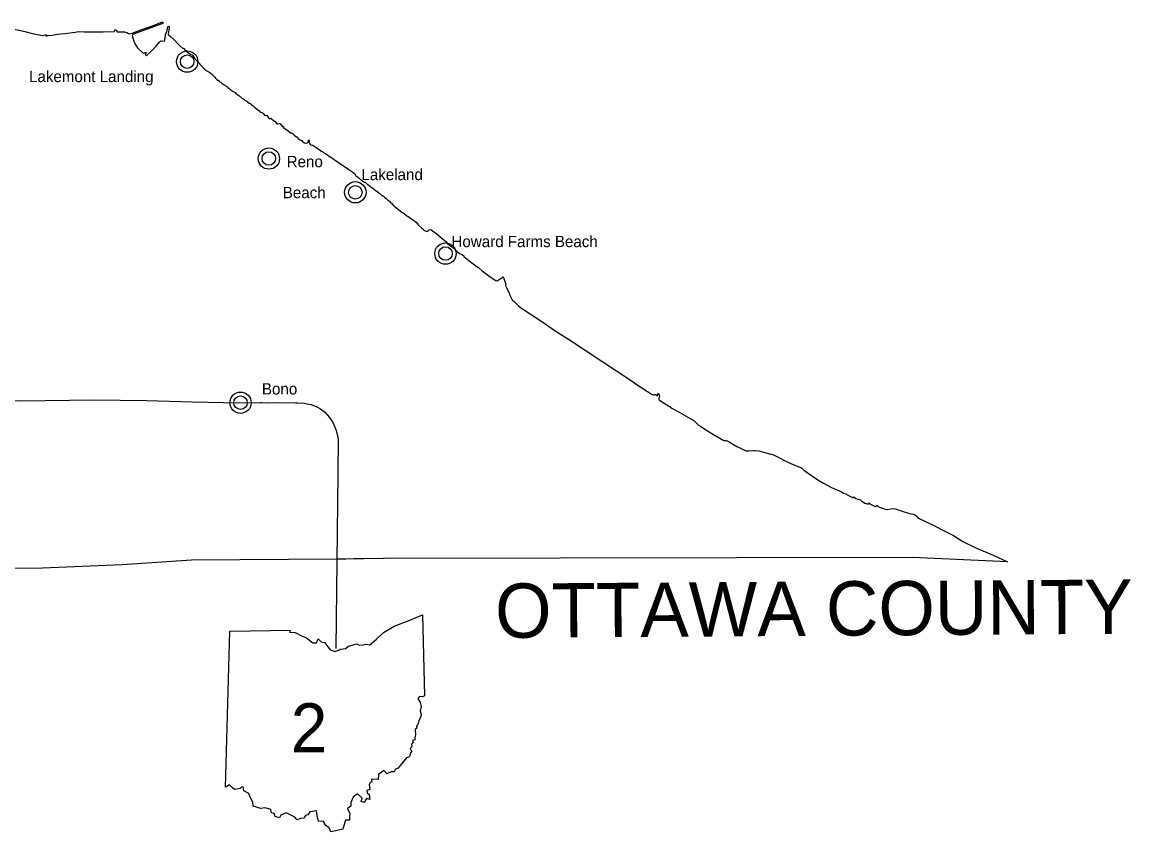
# Model space of a CAD drawing. Extents: x 0 to 750, y 0 to 507.
# Drawn here: x 515.6 to 617.7, y 213.2 to 287.8 of the extents above; entities that cross this region are included whole.
import ezdxf

# ---------------------------------------------------------------- set-up
doc = ezdxf.new("R2010")
doc.units = 0
for name, color, linetype in [('DV_X_Corp_Line', 7, 'Continuous'), ('GM_X_Adjacent_County_Text', 7, 'Continuous'), ('GM_X_County', 7, 'Continuous'), ('GM_X_Interstate_Route', 7, 'Continuous'), ('GM_X_State_Route', 7, 'Continuous')]:
    doc.layers.add(name, color=color, linetype=linetype)

msp = doc.modelspace()

# ---------------------------------------------------------------- linework, layer by layer
at = {"layer": 'DV_X_Corp_Line'}
for centre, radius in [((530.83, 284.15), 0.982), ((530.83, 284.15), 0.623), ((538.35, 275.22), 0.982), ((538.35, 275.22), 0.623), ((546.31, 272.11), 0.982), ((546.31, 272.11), 0.623), ((554.61, 266.47), 0.982), ((554.61, 266.47), 0.623), ((535.74, 252.73), 0.982), ((535.74, 252.73), 0.623)]:
    msp.add_circle(centre, radius, dxfattribs=at)
at = {"layer": 'GM_X_County'}
msp.add_lwpolyline([(514.76, 287.16), (515.77, 286.94), (516.58, 286.73), (517.19, 286.6), (517.49, 286.56), (517.6, 286.58), (517.77, 286.6), (517.83, 286.6), (517.9, 286.59), (517.91, 286.57), (517.83, 286.52), (517.86, 286.52), (517.94, 286.52), (518.03, 286.55), (518.39, 286.58), (518.9, 286.66), (519.19, 286.7), (519.58, 286.73), (520.53, 286.87), (520.87, 286.91), (521.38, 286.9), (521.62, 286.9), (522.02, 286.89), (522.31, 286.89), (522.6, 286.9), (523.1, 286.88), (524.1, 286.91), (524.13, 286.91), (524.16, 287.04), (524.18, 287.07), (524.24, 287.08), (524.3, 287.05), (524.34, 287), (524.35, 286.93), (524.38, 286.9), (524.92, 286.89), (525.07, 286.89), (525.28, 286.83), (525.42, 286.74), (525.49, 286.71), (525.78, 286.76), (526.57, 287.06), (527.21, 287.3), (527.8, 287.49), (528.5, 287.78), (528.55, 287.78), (528.6, 287.75), (528.62, 287.72), (528.6, 287.67), (525.81, 286.64), (525.79, 286.61), (525.77, 286.55), (525.82, 286.33), (525.91, 286.04), (526.06, 285.69), (526.27, 285.42), (526.75, 284.95), (526.83, 284.92), (526.91, 284.95), (526.98, 285), (527.03, 285.01), (527.05, 284.97), (526.98, 284.9), (526.97, 284.79), (527.07, 284.69), (527.15, 284.75), (527.19, 284.8), (527.46, 285.04), (527.98, 285.58), (528.1, 285.71), (528.27, 285.93), (528.36, 286.02), (528.44, 286.07), (528.74, 286.04), (528.86, 286.73), (528.92, 286.83), (528.96, 286.89), (529.01, 287.19), (529.04, 287.37), (529.07, 287.39), (529.13, 287.41), (529.17, 287.38), (529.18, 287.29), (529.14, 287.06), (529.09, 286.64), (529.12, 286.61), (529.26, 286.5), (529.53, 286.24), (530.1, 285.67), (530.41, 285.4), (530.45, 285.39), (530.52, 285.37), (530.54, 285.32), (530.6, 285.24), (530.7, 285.16), (530.76, 285.08), (530.8, 285.05), (530.88, 284.99), (530.96, 284.97), (531.17, 284.81), (531.3, 284.77), (531.33, 284.74), (531.38, 284.65), (531.5, 284.47), (531.6, 284.38), (531.6, 284.34), (531.7, 284.24), (531.91, 284.02), (531.95, 284), (531.95, 283.95), (532.09, 283.81), (532.37, 283.51), (532.45, 283.48), (532.44, 283.45), (532.5, 283.39), (532.91, 283.13), (533.03, 283.05), (533.17, 282.94), (533.24, 282.86), (533.31, 282.75), (533.38, 282.73), (533.37, 282.71), (533.45, 282.62), (533.56, 282.51), (533.65, 282.45), (533.72, 282.44), (533.72, 282.4), (533.79, 282.31), (533.92, 282.24), (534.03, 282.16), (534.17, 282.05), (534.27, 282), (534.32, 281.96), (534.44, 281.88), (534.5, 281.83), (534.56, 281.76), (534.64, 281.71), (534.71, 281.69), (534.72, 281.65), (534.83, 281.55), (534.9, 281.53), (534.92, 281.49), (535, 281.43), (535.14, 281.35), (535.25, 281.29), (535.31, 281.22), (535.54, 281.06), (535.85, 280.79), (535.98, 280.71), (536.03, 280.71), (536.17, 280.58), (536.25, 280.55), (536.29, 280.55), (536.41, 280.41), (536.55, 280.33), (536.6, 280.31), (536.71, 280.2), (536.89, 280.09), (537.02, 279.95), (537.42, 279.65), (537.56, 279.5), (537.73, 279.45), (537.82, 279.37), (537.96, 279.23), (538.06, 279.17), (538.1, 279.2), (538.15, 279.19), (538.33, 278.98), (538.48, 278.89), (538.52, 278.93), (538.6, 278.88), (538.74, 278.75), (538.86, 278.65), (538.89, 278.67), (538.94, 278.62), (539.04, 278.49), (539.13, 278.43), (539.19, 278.43), (539.29, 278.45), (539.36, 278.44), (539.57, 278.21), (539.63, 278.17), (539.69, 278.17), (539.7, 278.15), (539.68, 278.12), (539.84, 277.97), (540.09, 277.81), (540.34, 277.6), (540.4, 277.59), (540.43, 277.59), (540.51, 277.52), (540.58, 277.49), (540.63, 277.49), (540.69, 277.38), (540.89, 277.23), (540.96, 277.18), (541.05, 277.08), (541.31, 276.89), (541.38, 276.87), (541.46, 276.8), (541.64, 276.68), (541.8, 276.65), (541.92, 276.66), (541.97, 276.74), (542.01, 276.92), (542.07, 276.9), (542.06, 276.69), (542.13, 276.57), (542.19, 276.49), (542.36, 276.44), (542.43, 276.42), (542.68, 276.27), (543.19, 275.91), (543.42, 275.77), (543.87, 275.47), (544.86, 274.78), (545.72, 274.2), (546.08, 273.96), (546.27, 273.81), (546.31, 273.75), (546.37, 273.62), (546.4, 273.61), (546.5, 273.55), (546.55, 273.51), (546.62, 273.44), (546.75, 273.32), (546.8, 273.3), (546.98, 273.16), (547.09, 273.07), (547.13, 273.05), (547.18, 273.06), (547.25, 273), (547.41, 272.86), (547.47, 272.82), (547.59, 272.75), (547.73, 272.61), (547.83, 272.55), (547.88, 272.52), (548.1, 272.33), (548.21, 272.28), (548.33, 272.18), (548.43, 272.09), (548.51, 272.04), (548.56, 272), (548.73, 271.84), (548.8, 271.8), (548.86, 271.79), (548.96, 271.7), (549.03, 271.63), (549.14, 271.54), (549.22, 271.49), (549.27, 271.43), (549.4, 271.34), (549.47, 271.32), (549.46, 271.28), (549.52, 271.2), (549.67, 271.08), (549.8, 270.92), (550.24, 270.56), (550.49, 270.34), (550.64, 270.25), (550.76, 270.19), (550.85, 270.12), (551.06, 269.94), (551.14, 269.91), (551.28, 269.83), (551.78, 269.45), (551.96, 269.29), (552.1, 269.12), (552.43, 268.82), (552.75, 268.57), (552.92, 268.51), (552.99, 268.52), (553.04, 268.59), (553.1, 268.65), (553.19, 268.68), (553.28, 268.66), (553.73, 268.35), (554.63, 267.58), (554.79, 267.4), (555.17, 267.1), (555.26, 267.05), (555.33, 266.96), (555.38, 266.94), (555.64, 266.69), (555.91, 266.48), (556.04, 266.4), (556.15, 266.37), (556.29, 266.25), (556.31, 266.2), (556.62, 265.96), (556.76, 265.83), (557.29, 265.43), (557.56, 265.23), (557.61, 265.22), (557.71, 265.12), (558, 264.89), (558.72, 264.34), (559.23, 264), (559.36, 263.97), (559.46, 264.03), (559.82, 264.28), (559.89, 264.33), (559.93, 264.32), (559.96, 264.25), (560.07, 263.91), (560.17, 263.68), (560.15, 263.64), (560.13, 263.59), (560.12, 263.54), (560.25, 263.28), (560.46, 262.82), (560.53, 262.63), (560.61, 262.44), (560.76, 262.22), (560.95, 262.01), (561.33, 261.67), (561.62, 261.43), (563.29, 260.33), (563.8, 260), (564.81, 259.3), (565.93, 258.6), (568.99, 256.56), (571.7, 254.77), (572.25, 254.39), (573.65, 253.48), (573.76, 253.45), (573.84, 253.46), (573.92, 253.51), (574.06, 253.41), (574.1, 253.41), (574.15, 253.41), (574.13, 253.48), (574.12, 253.52), (574.16, 253.56), (574.2, 253.57), (574.29, 253.46), (574.31, 253.29), (574.28, 253.21), (574.25, 253.11), (574.25, 253.04), (574.41, 252.91), (575.22, 252.39), (575.29, 252.38), (575.33, 252.32), (575.45, 252.22), (576.12, 251.85), (576.78, 251.48), (576.99, 251.38), (577.48, 251.09), (577.7, 250.87), (577.86, 250.71), (578.08, 250.56), (578.49, 250.3), (579.28, 249.82), (580.22, 249.26), (580.33, 249.26), (580.48, 249.24), (580.71, 249.13), (581.42, 248.71), (581.84, 248.52), (582.13, 248.36), (582.25, 248.31), (582.54, 248.31), (582.98, 248.34), (583.13, 248.34), (583.44, 248.29), (584.22, 248.1), (584.57, 247.99), (584.73, 247.97), (585.04, 247.82), (585.31, 247.69), (585.94, 247.36), (586.69, 247), (587.37, 246.74), (587.61, 246.52), (588.31, 246.02), (588.49, 245.9), (588.89, 245.62), (589.41, 245.31), (590.14, 244.93), (590.79, 244.64), (590.82, 244.66), (590.99, 244.56), (591.13, 244.48), (591.26, 244.41), (591.38, 244.36), (591.49, 244.34), (591.48, 244.31), (591.7, 244.2), (591.94, 244.06), (592.15, 243.98), (592.21, 244.08), (592.39, 243.92), (592.8, 243.78), (592.9, 243.71), (593.22, 243.49), (593.54, 243.4), (593.58, 243.5), (593.72, 243.4), (593.92, 243.31), (594.09, 243.21), (594.24, 243.19), (594.29, 243.24), (594.32, 243.28), (594.36, 243.3), (594.37, 243.25), (594.42, 243.17), (594.57, 243.1), (594.92, 242.99), (595.1, 242.92), (595.3, 242.89), (595.58, 242.95), (595.82, 242.98), (596, 242.95), (596.73, 242.7), (597.33, 242.53), (597.7, 242.48), (597.79, 242.45), (597.88, 242.38), (598, 242.24), (598.09, 242.14), (598.27, 242.05), (598.68, 241.86), (599.68, 241.35), (600.47, 240.97), (601.39, 240.49), (602.23, 239.96), (603.48, 239.35), (605.04, 238.69), (606.34, 238.09), (597.6, 238.48), (548.96, 238.38), (548.84, 238.38), (547.11, 238.35), (546.2, 238.35), (545.43, 238.34), (544.61, 238.32), (531.24, 238.24), (524.85, 237.8), (517.5, 237.5), (504.51, 237.37)], dxfattribs=at)
at = {"layer": 'GM_X_Interstate_Route'}
msp.add_line((534.37, 217.32), (534.77, 231.68), dxfattribs=at)
msp.add_line((534.37, 217.32), (534.77, 231.68), dxfattribs=at)
for points in [[(534.77, 231.68), (540.34, 231.78), (540.26, 231.6), (540.78, 231.57), (541.34, 231.26), (541.81, 231.07), (542.39, 230.61), (542.74, 230.61), (542.88, 230.99), (543.15, 230.7), (543.46, 230.65), (544, 229.96), (544.45, 229.81), (544.99, 230.05), (545.39, 230.09), (545.69, 230.32), (546.45, 230.52), (546.66, 230.4), (547.07, 230.42), (547.27, 230.51), (547.63, 230.43), (548.25, 230.95), (548.89, 231.57), (549.87, 232.15), (551.34, 232.7), (552.5, 233.19), (552.67, 225.74)], [(534.77, 231.68), (540.34, 231.78), (540.26, 231.6), (540.78, 231.57), (541.34, 231.26), (541.81, 231.07), (542.39, 230.61), (542.74, 230.61), (542.88, 230.99), (543.15, 230.7), (543.46, 230.65), (544, 229.96), (544.45, 229.81), (544.99, 230.05), (545.39, 230.09), (545.69, 230.32), (546.45, 230.52), (546.66, 230.4), (547.07, 230.42), (547.27, 230.51), (547.63, 230.43), (548.25, 230.95), (548.89, 231.57), (549.87, 232.15), (551.34, 232.7), (552.5, 233.19), (552.67, 225.74)], [(552.67, 225.74), (552.5, 225.64), (552.23, 225.68), (552.05, 225.48), (552.28, 225.13), (552.38, 224.76), (552.29, 224.35), (552.38, 224.02), (552.32, 223.74), (552.15, 223.46), (552.09, 223.19), (551.95, 222.91), (551.96, 222.75), (551.82, 222.63), (551.85, 222.16), (551.78, 221.91), (551.8, 221.68), (551.58, 221.62), (551.63, 221.44), (551.49, 221.3), (551.52, 221.05), (551.36, 220.9), (551.52, 220.58), (551.39, 220.49), (551.29, 220.11), (551.01, 220.03), (550.44, 219.33), (550.24, 219.07), (550.02, 219), (549.89, 218.73), (549.62, 218.73), (549.2, 218.55), (548.93, 218.87), (548.45, 218.48), (548.4, 218.03), (547.8, 218.05), (547.82, 217.82), (547.69, 217.75), (547.57, 217.53), (547.64, 217.12), (547.36, 217.02), (547.39, 216.79), (547.57, 216.64), (547.65, 216.2), (547.35, 216.29), (547.11, 215.91), (546.86, 216), (546.94, 216.32), (546.51, 216.7), (546.11, 216.4), (545.9, 215.9), (545.9, 215.57), (545.6, 215.37), (545.79, 214.91), (545.76, 214.58), (545.76, 214.28), (545.39, 214.29), (545.16, 213.47)], [(552.67, 225.74), (552.5, 225.64), (552.23, 225.68), (552.05, 225.48), (552.28, 225.13), (552.38, 224.76), (552.29, 224.35), (552.38, 224.02), (552.32, 223.74), (552.15, 223.46), (552.09, 223.19), (551.95, 222.91), (551.96, 222.75), (551.82, 222.63), (551.85, 222.16), (551.78, 221.91), (551.8, 221.68), (551.58, 221.62), (551.63, 221.44), (551.49, 221.3), (551.52, 221.05), (551.36, 220.9), (551.52, 220.58), (551.39, 220.49), (551.29, 220.11), (551.01, 220.03), (550.44, 219.33), (550.24, 219.07), (550.02, 219), (549.89, 218.73), (549.62, 218.73), (549.2, 218.55), (548.93, 218.87), (548.45, 218.48), (548.4, 218.03), (547.8, 218.05), (547.82, 217.82), (547.69, 217.75), (547.57, 217.53), (547.64, 217.12), (547.36, 217.02), (547.39, 216.79), (547.57, 216.64), (547.65, 216.2), (547.35, 216.29), (547.11, 215.91), (546.86, 216), (546.94, 216.32), (546.51, 216.7), (546.11, 216.4), (545.9, 215.9), (545.9, 215.57), (545.6, 215.37), (545.79, 214.91), (545.76, 214.58), (545.76, 214.28), (545.39, 214.29), (545.16, 213.47)], [(545.16, 213.47), (544.51, 213.31), (544.06, 213.21), (543.9, 213.59), (543.58, 213.79), (543.37, 214.16), (542.91, 214.21), (542.8, 214.73), (542.74, 215.15), (542.11, 215.05), (541.94, 214.79), (541.71, 214.72), (541.58, 214.46), (541.27, 214.44), (540.95, 214.32), (540.73, 214.57), (540.19, 214.83), (539.95, 214.96), (539.44, 214.76), (539.34, 214.51), (538.93, 214.62), (538.84, 214.89), (538.59, 214.97), (538.54, 215.26), (538.02, 215.41), (537.62, 215.35), (536.92, 215.58), (536.87, 215.96), (536.63, 216.41), (536.51, 216.73), (536.06, 216.98), (535.97, 217.35), (535.83, 217.34), (535.7, 217.19), (535.21, 217.12), (535.01, 217.27), (534.73, 217.54), (534.37, 217.32)], [(545.16, 213.47), (544.51, 213.31), (544.06, 213.21), (543.9, 213.59), (543.58, 213.79), (543.37, 214.16), (542.91, 214.21), (542.8, 214.73), (542.74, 215.15), (542.11, 215.05), (541.94, 214.79), (541.71, 214.72), (541.58, 214.46), (541.27, 214.44), (540.95, 214.32), (540.73, 214.57), (540.19, 214.83), (539.95, 214.96), (539.44, 214.76), (539.34, 214.51), (538.93, 214.62), (538.84, 214.89), (538.59, 214.97), (538.54, 215.26), (538.02, 215.41), (537.62, 215.35), (536.92, 215.58), (536.87, 215.96), (536.63, 216.41), (536.51, 216.73), (536.06, 216.98), (535.97, 217.35), (535.83, 217.34), (535.7, 217.19), (535.21, 217.12), (535.01, 217.27), (534.73, 217.54), (534.37, 217.32)]]:
    msp.add_lwpolyline(points, dxfattribs=at)
at = {"layer": 'GM_X_State_Route'}
for points in [[(495.54, 252.94), (508.9, 252.95), (515.51, 252.91), (522.24, 252.99)], [(522.24, 252.99), (527.09, 252.93), (531.28, 252.8), (535.6, 252.72), (537.57, 252.74), (537.7, 252.74)], [(537.7, 252.74), (538.23, 252.73), (538.91, 252.74), (540.8, 252.73)], [(540.8, 252.73), (540.99, 252.73), (541.59, 252.7), (542.02, 252.61), (542.23, 252.57), (542.77, 252.36), (543.1, 252.16), (543.49, 251.86), (543.93, 251.37), (544.13, 251.1), (544.27, 250.85), (544.52, 250.27), (544.62, 249.96), (544.72, 249.4), (544.69, 246.18)], [(544.69, 246.18), (544.53, 230.09)]]:
    msp.add_lwpolyline(points, dxfattribs=at)

# ---------------------------------------------------------------- texts
at = {"layer": 'DV_X_Corp_Line'}
for s, height, p in [('Lakemont Landing', 1.0417, (516.27, 282.26)), ('Reno', 1.042, (539.99, 274.42)), ('Lakeland', 1.042, (546.87, 273.23)), ('Beach', 1.042, (539.63, 271.57)), ('Howard Farms Beach', 1.0417, (555.16, 267.06)), ('Bono', 1.042, (537.71, 253.49))]:
    msp.add_text(s, height=height, rotation=0, dxfattribs=at).set_placement(p)
at = {"layer": 'GM_X_Adjacent_County_Text'}
msp.add_text('OTTAWA COUNTY', height=5, rotation=0.3824, dxfattribs=at).set_placement((559.19, 231.07))
at = {"layer": 'GM_X_Interstate_Route'}
msp.add_text('2', height=4.53, dxfattribs=at).set_placement((540.37, 220.52))

doc.saveas('drawing.dxf')
